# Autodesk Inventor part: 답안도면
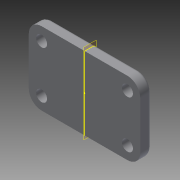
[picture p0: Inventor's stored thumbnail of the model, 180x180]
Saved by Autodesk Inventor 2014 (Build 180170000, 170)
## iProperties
Created: 2015-08
Part Number: 답안도면
Material: 일반
Document SubType Name: Modeling
Designer: SEC
Density: 1 g/cm^3
Appearance: 기본값
Author: SEC
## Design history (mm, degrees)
sketch "스케치1"
  geometry: L1 (47, -40)-(-47, -40); L2 (-61, -26)-(-61, 26); L3 (-47, 40)-(47, 40); L4 (61, 26)-(61, -26); C1 r 6 at (47, -26); C2 r 6 at (-47, -26); C3 r 6 at (-47, 26); C4 r 6 at (47, 26); A1 r 14 centre (47, -26) between (47, -40) and (61, -26); A2 r 14 centre (-47, -26) between (-61, -26) and (-47, -40); A3 r 14 centre (-47, 26) between (-47, 40) and (-61, 26); A4 r 14 centre (47, 26) between (61, 26) and (47, 40); 6 further points
  constraints: 8 centre point, 8 end point, 8 point on circle, 8 tangent, 6 point on line, 4 coincident, 3 equal radius, 2 midpoint, 2 parallel, 1 horizontal, 1 horizontal alignment, 1 perpendicular, 1 vertical alignment
  dimensions: "d0" = 122 distance of point (-61, 40) point (61, 40); "d1" = 80 distance of point (-61, -40) point (-61, 40); "d2" = 14 radius of A1; "d3" = 12 diameter of C1; "d4" = 12 diameter of C2; "d5" = 12 diameter of C3; "d6" = 12 diameter of C4
extrude "돌출1" new body sketch "스케치1" distance "d7" = 12; taper "d8" = 0 deg
fillet "모깎기1" dims "d9" = 3
node "작업 평면1"
sketch "스케치2"
  geometry: L1 (-11, 12)-(63, 12) reference; L2 (66, 9)-(66, 0) reference; L3 (66, 0)-(-14, 0) reference; L4 (-14, 0)-(-14, 9) reference; A1 r 3 centre (-11, 9) between (-11, 12) and (-14, 9) reference; A2 r 3 centre (63, 9) between (66, 9) and (63, 12) reference; 1 further point
  node "절단 모서리 투영1"
node "솔리드1"
